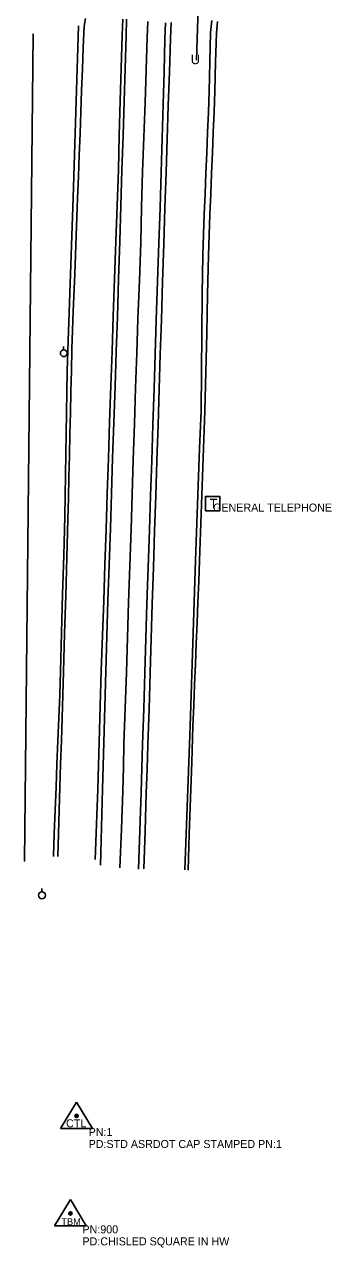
# Model space of a CAD drawing. Extents: x 1445297 to 1476720, y 2042269 to 2057889.
# Drawn here: x 1445986 to 1446178, y 2042269 to 2043034 of the extents above; entities that cross this region are included whole.
import ezdxf

# ---------------------------------------------------------------- set-up
doc = ezdxf.new("R2010")
doc.units = 0
for name, color, linetype in [('S_DITCHLINE', 7, 'Continuous'), ('S_EDGE_PAVEMENT', 7, 'Continuous'), ('S_PAVEMENT_CROWN', 7, 'Continuous'), ('S_PRIMARY_CTL', 7, 'Continuous'), ('S_PRIMARY_CTL_ANNOT', 7, 'Continuous'), ('S_SHOULDER', 7, 'Continuous'), ('S_TELEPHONE_UTILITIES', 7, 'Continuous'), ('S_TELEPHONE_UTILITIES_ANNOT', 7, 'Continuous'), ('S_UNDERGROUND_CABLE', 7, 'Continuous'), ('S_UTILITY_POLE', 7, 'Continuous'), ('S_UTL_PT_SYM', 7, 'Continuous'), ('S_WATER_UTILITIES', 7, 'Continuous')]:
    doc.layers.add(name, color=color, linetype=linetype)

msp = doc.modelspace()

# ---------------------------------------------------------------- linework, layer by layer
at = {"layer": 'S_DITCHLINE'}
for points in [[(1446023.83, 2043037.3), (1446022.97, 2043032.53), (1446022.47, 2043019.1), (1446021.96, 2043005.66), (1446021.46, 2042992.23), (1446020.96, 2042978.8), (1446020.46, 2042965.37), (1446019.96, 2042951.93), (1446019.45, 2042938.5), (1446018.95, 2042925.07), (1446018.05, 2042901.46), (1446017.14, 2042877.84), (1446016.23, 2042854.23), (1446015.33, 2042830.62), (1446015.03, 2042817.35), (1446014.73, 2042804.07), (1446014.42, 2042790.8), (1446014.12, 2042777.52), (1446013.82, 2042764.25), (1446013.52, 2042750.97), (1446013.22, 2042737.7), (1446012.91, 2042724.42), (1446012.2, 2042700.59), (1446011.49, 2042676.76), (1446010.77, 2042652.94), (1446010.06, 2042629.11), (1446009.63, 2042614.68), (1446009.2, 2042600.25), (1446008.77, 2042585.82), (1446008.34, 2042571.4), (1446007.91, 2042556.97), (1446007.48, 2042542.54), (1446007.05, 2042528.11), (1446006.62, 2042513.69)], [(1446086.04, 2042505.34), (1446086.84, 2042527.79), (1446087.64, 2042550.24), (1446088.43, 2042572.69), (1446089.23, 2042595.14), (1446089.64, 2042608.09), (1446090.06, 2042621.03), (1446090.47, 2042633.97), (1446090.88, 2042646.92), (1446091.3, 2042659.86), (1446091.71, 2042672.81), (1446092.13, 2042685.75), (1446092.54, 2042698.69), (1446093.43, 2042722.03), (1446094.32, 2042745.37), (1446095.21, 2042768.71), (1446096.1, 2042792.05), (1446096.35, 2042816.42), (1446096.6, 2042840.78), (1446096.85, 2042865.14), (1446097.1, 2042889.5), (1446097.61, 2042902.27), (1446098.12, 2042915.04), (1446098.63, 2042927.81), (1446099.14, 2042940.57), (1446099.66, 2042953.34), (1446100.17, 2042966.11), (1446100.68, 2042978.88), (1446101.19, 2042991.65), (1446101.58, 2043010.11), (1446101.97, 2043028.57), (1446102.88, 2043036.01)], [(1446087.94, 2042505.14), (1446088.7, 2042527.6), (1446089.47, 2042550.07), (1446090.23, 2042572.53), (1446091, 2042595), (1446091.52, 2042607.94), (1446092.04, 2042620.89), (1446092.56, 2042633.83), (1446093.07, 2042646.78), (1446093.59, 2042659.73), (1446094.11, 2042672.67), (1446094.63, 2042685.62), (1446095.15, 2042698.57), (1446096, 2042721.93), (1446096.84, 2042745.29), (1446097.69, 2042768.65), (1446098.54, 2042792.02), (1446099.06, 2042816.31), (1446099.59, 2042840.6), (1446100.11, 2042864.89), (1446100.64, 2042889.18), (1446101.14, 2042902.03), (1446101.65, 2042914.87), (1446102.15, 2042927.71), (1446102.66, 2042940.56), (1446103.17, 2042953.4), (1446103.67, 2042966.24), (1446104.18, 2042979.09), (1446104.68, 2042991.93), (1446105.19, 2043010.02), (1446105.7, 2043028.12), (1446106.39, 2043035.48)], [(1446019.42, 2043032.67), (1446019.01, 2043019.27), (1446018.6, 2043005.87), (1446018.19, 2042992.47), (1446017.78, 2042979.08), (1446017.37, 2042965.68), (1446016.96, 2042952.28), (1446016.55, 2042938.88), (1446016.14, 2042925.49), (1446015.29, 2042901.57), (1446014.43, 2042877.65), (1446013.58, 2042853.73), (1446012.73, 2042829.82), (1446012.5, 2042816.85), (1446012.27, 2042803.88), (1446012.04, 2042790.91), (1446011.81, 2042777.94), (1446011.58, 2042764.97), (1446011.35, 2042752), (1446011.12, 2042739.03), (1446010.89, 2042726.06), (1446010.24, 2042701.84), (1446009.59, 2042677.62), (1446008.95, 2042653.4), (1446008.3, 2042629.18), (1446007.74, 2042614.74), (1446007.17, 2042600.3), (1446006.6, 2042585.86), (1446006.04, 2042571.43), (1446005.47, 2042556.99), (1446004.9, 2042542.55), (1446004.34, 2042528.11), (1446003.77, 2042513.68)]]:
    msp.add_lwpolyline(points, dxfattribs=at)
at = {"layer": 'S_EDGE_PAVEMENT'}
for points in [[(1446049.58, 2043036.92), (1446049.31, 2043026.44), (1446048.67, 2043006.1), (1446048.03, 2042985.76), (1446047.34, 2042964.15), (1446046.66, 2042942.54), (1446045.99, 2042920.35), (1446045.32, 2042898.17), (1446044.54, 2042874.51), (1446043.77, 2042850.85), (1446043.04, 2042829.08), (1446042.31, 2042807.31), (1446041.51, 2042784.91), (1446040.72, 2042762.52), (1446040.07, 2042740.55), (1446039.42, 2042718.57), (1446038.66, 2042696.01), (1446037.9, 2042673.45), (1446037.25, 2042651.42), (1446036.6, 2042629.39), (1446036, 2042607.17), (1446035.4, 2042584.96), (1446034.93, 2042570.33), (1446034.45, 2042555.7), (1446033.81, 2042531.95), (1446033.17, 2042508.19)], [(1446073.85, 2043034.53), (1446073.51, 2043024.49), (1446072.93, 2043004.11), (1446072.35, 2042983.74), (1446071.74, 2042962.52), (1446071.14, 2042941.3), (1446070.46, 2042919.07), (1446069.79, 2042896.84), (1446068.94, 2042872.95), (1446068.1, 2042849.07), (1446067.4, 2042827.55), (1446066.69, 2042806.04), (1446066.02, 2042783.46), (1446065.35, 2042760.88), (1446064.58, 2042739.21), (1446063.82, 2042717.55), (1446063.06, 2042694.49), (1446062.3, 2042671.44), (1446061.6, 2042649.94), (1446060.89, 2042628.44), (1446060.23, 2042606), (1446059.57, 2042583.56), (1446059.07, 2042568.67), (1446058.58, 2042553.78), (1446057.83, 2042529.79), (1446057.08, 2042505.81)]]:
    msp.add_lwpolyline(points, dxfattribs=at)
at = {"layer": 'S_PAVEMENT_CROWN'}
msp.add_lwpolyline([(1446062.89, 2043035.53), (1446062.44, 2043025.53), (1446061.77, 2043005.2), (1446061.1, 2042984.87), (1446060.25, 2042963.22), (1446059.41, 2042941.58), (1446058.93, 2042919.49), (1446058.45, 2042897.4), (1446057.52, 2042873.57), (1446056.6, 2042849.74), (1446055.86, 2042828.15), (1446055.12, 2042806.56), (1446054.4, 2042784.01), (1446053.68, 2042761.46), (1446053.03, 2042739.87), (1446052.39, 2042718.28), (1446051.51, 2042695.28), (1446050.64, 2042672.28), (1446050.07, 2042650.44), (1446049.5, 2042628.6), (1446048.71, 2042606.31), (1446047.92, 2042584.01), (1446047.58, 2042569.38), (1446047.24, 2042554.74), (1446046.28, 2042530.69), (1446045.33, 2042506.64)], dxfattribs=at)
at = {"layer": 'S_PRIMARY_CTL'}
for p, q in [((1446018.33, 2042360.18), (1446008.3, 2042343.67)), ((1446018.33, 2042360.18), (1446028.16, 2042343.67)), ((1446008.3, 2042343.67), (1446028.16, 2042343.67)), ((1446014.47, 2042299.34), (1446004.43, 2042282.83)), ((1446014.47, 2042299.34), (1446024.29, 2042282.83)), ((1446004.43, 2042282.83), (1446024.29, 2042282.83))]:
    msp.add_line(p, q, dxfattribs=at)
for centre, radius in [((1446018.33, 2042351.48), 1.04), ((1446018.33, 2042351.48), 0.609), ((1446018.33, 2042351.48), 0.344), ((1446014.47, 2042290.64), 1.04), ((1446014.47, 2042290.64), 0.609), ((1446014.47, 2042290.64), 0.344)]:
    msp.add_circle(centre, radius, dxfattribs=at)
at = {"layer": 'S_SHOULDER'}
for points in [[(1446047.13, 2043036.97), (1446046.78, 2043026.92), (1446046.14, 2043006.39), (1446045.5, 2042985.86), (1446044.96, 2042964.31), (1446044.41, 2042942.77), (1446043.65, 2042920.5), (1446042.9, 2042898.23), (1446042.04, 2042874.72), (1446041.19, 2042851.21), (1446040.44, 2042829.45), (1446039.7, 2042807.7), (1446038.95, 2042785.14), (1446038.19, 2042762.57), (1446037.47, 2042740.3), (1446036.74, 2042718.03), (1446036, 2042695.86), (1446035.25, 2042673.68), (1446034.48, 2042651.66), (1446033.7, 2042629.63), (1446033.11, 2042607.49), (1446032.51, 2042585.35), (1446032.02, 2042570.57), (1446031.54, 2042555.8), (1446030.69, 2042533.8), (1446029.83, 2042511.81)], [(1446077.34, 2043034.74), (1446076.95, 2043024.75), (1446076.27, 2043003.76), (1446075.59, 2042982.76), (1446074.93, 2042962), (1446074.27, 2042941.24), (1446073.54, 2042918.86), (1446072.82, 2042896.47), (1446072.05, 2042872.76), (1446071.28, 2042849.05), (1446070.62, 2042827.42), (1446069.97, 2042805.79), (1446069.24, 2042783.39), (1446068.5, 2042760.98), (1446067.74, 2042739.01), (1446066.99, 2042717.04), (1446066.28, 2042694.29), (1446065.58, 2042671.55), (1446064.91, 2042649.94), (1446064.25, 2042628.33), (1446063.56, 2042605.9), (1446062.86, 2042583.47), (1446062.37, 2042568.4), (1446061.88, 2042553.32), (1446061.12, 2042529.6), (1446060.36, 2042505.87)]]:
    msp.add_lwpolyline(points, dxfattribs=at)
at = {"layer": 'S_TELEPHONE_UTILITIES'}
msp.add_lwpolyline([(1446098.87, 2042729.67), (1446098.87, 2042738.67), (1446107.87, 2042738.67), (1446107.87, 2042729.67)], close=True, dxfattribs=at)
at = {"layer": 'S_UNDERGROUND_CABLE'}
msp.add_line((1446099.35, 2043214.92), (1446093.27, 2043011.34), dxfattribs=at)
at = {"layer": 'S_UTILITY_POLE'}
for p, q in [((1446010.17, 2042830.27), (1446010.17, 2042832.38)), ((1445996.52, 2042491.54), (1445996.52, 2042493.65))]:
    msp.add_line(p, q, dxfattribs=at)
for centre in [(1446010.3, 2042828.13), (1445996.64, 2042489.4)]:
    msp.add_circle(centre, 2.13, dxfattribs=at)
at = {"layer": 'S_UTL_PT_SYM'}
for points in [[(1445991.08, 2043027.56), (1445991.08, 2043027.61), (1445991.08, 2043027.56), (1445991.03, 2043027.56), (1445991.08, 2043027.56), (1445991.08, 2043027.51), (1445991.08, 2043027.56), (1445991.13, 2043027.56)], [(1445985.78, 2042510.78), (1445985.78, 2042510.83), (1445985.78, 2042510.78), (1445985.73, 2042510.78), (1445985.78, 2042510.78), (1445985.78, 2042510.73), (1445985.78, 2042510.78), (1445985.83, 2042510.78)]]:
    msp.add_lwpolyline(points, dxfattribs=at)
at = {"layer": 'S_WATER_UTILITIES'}
msp.add_line((1445985.78, 2042510.78), (1445991.08, 2043027.56), dxfattribs=at)

# ---------------------------------------------------------------- texts
at = {"layer": 'S_PRIMARY_CTL'}
for s, height, p in [('CTL', 5, (1446011.74, 2042344.4)), ('TBM', 4.287, (1446008.81, 2042283.26))]:
    msp.add_text(s, height=height, dxfattribs=at).set_placement(p)
at = {"layer": 'S_PRIMARY_CTL_ANNOT'}
for s, p in [('PN:1', (1446025.83, 2042338.98)), ('PD:STD ASRDOT CAP STAMPED PN:1', (1446025.83, 2042331.48)), ('PN:900', (1446021.97, 2042278.14)), ('PD:CHISLED SQUARE IN HW', (1446021.97, 2042270.64))]:
    msp.add_text(s, height=5, dxfattribs=at).set_placement(p)
at = {"layer": 'S_TELEPHONE_UTILITIES'}
msp.add_text('T', height=6, dxfattribs=at).set_placement((1446101.43, 2042731.17))
at = {"layer": 'S_TELEPHONE_UTILITIES_ANNOT'}
msp.add_text('GENERAL TELEPHONE', height=5, dxfattribs=at).set_placement((1446103.6, 2042729.19))
at = {"layer": 'S_UTL_PT_SYM'}
msp.add_text('U', height=6, dxfattribs=at).set_placement((1446089.64, 2043008.79))

doc.saveas('drawing.dxf')
